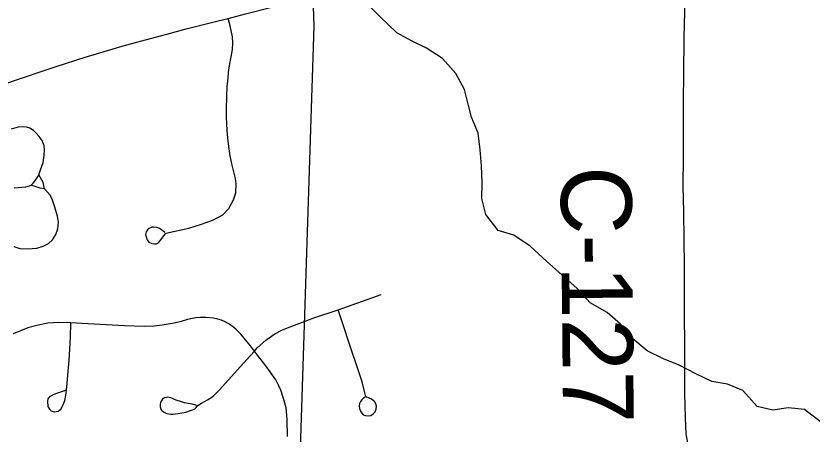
# Model space of a CAD drawing. Extents: x 0 to 34, y -5 to 22.
# Drawn here: x 2.395 to 3.035, y 19.735 to 20.071 of the extents above; entities that cross this region are included whole.
import ezdxf

# ---------------------------------------------------------------- set-up
doc = ezdxf.new("R2010")
doc.units = 0
for name, color, linetype in [('GM_X_City_Street', 7, 'Continuous'), ('GM_X_County_Road', 7, 'Continuous'), ('GM_X_County_Road_Text', 7, 'Continuous'), ('GM_X_Minor_River', 7, 'Continuous'), ('GM_X_Rail_Line', 7, 'Continuous'), ('GM_X_State_Route', 7, 'Continuous')]:
    doc.layers.add(name, color=color, linetype=linetype)

msp = doc.modelspace()

# ---------------------------------------------------------------- linework, layer by layer
at = {"layer": 'GM_X_City_Street'}
for points in [[(2.51469, 19.89713), (2.51174, 19.89956), (2.51027, 19.90044), (2.50828, 19.90133), (2.50571, 19.90162), (2.50416, 19.9014), (2.5021, 19.90044), (2.50062, 19.89934), (2.49974, 19.89787), (2.49923, 19.89559), (2.49952, 19.89368), (2.50033, 19.89146), (2.50181, 19.88955), (2.50409, 19.8883), (2.50622, 19.88801), (2.50784, 19.88815), (2.50968, 19.88903), (2.51123, 19.89102), (2.51321, 19.89375), (2.51534, 19.89661), (2.53404, 19.90067), (2.54398, 19.90383), (2.55376, 19.90744), (2.5612, 19.91156), (2.5662, 19.91656), (2.56981, 19.92348), (2.57165, 19.92908), (2.57209, 19.93636), (2.57136, 19.94078), (2.56878, 19.95138), (2.56724, 19.95881), (2.56605, 19.96646), (2.5654, 19.97324), (2.56473, 19.97934), (2.56414, 19.99031), (2.56422, 19.99613), (2.56436, 20.00687), (2.56466, 20.01438), (2.56547, 20.02159), (2.56591, 20.02579), (2.56657, 20.03145), (2.56804, 20.03859), (2.569, 20.04433), (2.56937, 20.04978), (2.56915, 20.05449), (2.56709, 20.06347), (2.56544, 20.06946)], [(2.39351, 19.9331), (2.40293, 19.9339), (2.40603, 19.9347), (2.40736, 19.9354), (2.40885, 19.93695), (2.41074, 19.93941), (2.41287, 19.94263), (2.41346, 19.94352), (2.41487, 19.94772), (2.41691, 19.95364), (2.41773, 19.95926), (2.41804, 19.96396), (2.41773, 19.96702), (2.41609, 19.9711), (2.41374, 19.97447), (2.4112, 19.97713), (2.40905, 19.97928), (2.40609, 19.98111), (2.40344, 19.98192), (2.40014, 19.98225), (2.39669, 19.98203), (2.39114, 19.9804)], [(2.39334, 19.88588), (2.39805, 19.88439), (2.40431, 19.8841), (2.41189, 19.88461), (2.41689, 19.88634), (2.4212, 19.88835), (2.4243, 19.8914), (2.42717, 19.8957), (2.42872, 19.90013), (2.42918, 19.90541), (2.42832, 19.91041), (2.42636, 19.91747), (2.42441, 19.92327), (2.42241, 19.9273), (2.41804, 19.93229), (2.41747, 19.93505), (2.41678, 19.93746), (2.41346, 19.94352)], [(2.41804, 19.93229), (2.41436, 19.93287), (2.40897, 19.93482), (2.40736, 19.9354)], [(2.54063, 19.75812), (2.53666, 19.75906), (2.53337, 19.75973), (2.53046, 19.76033), (2.52713, 19.76121), (2.52445, 19.76212), (2.5223, 19.76298), (2.52032, 19.76388), (2.5193, 19.76426), (2.51822, 19.76458), (2.51711, 19.76465), (2.51594, 19.76458), (2.51431, 19.76418), (2.51365, 19.76378), (2.51282, 19.76321), (2.51222, 19.76242), (2.51175, 19.76167), (2.51114, 19.76035), (2.51082, 19.75916), (2.51091, 19.75705), (2.5114, 19.7552), (2.51191, 19.75434), (2.51239, 19.7538), (2.51402, 19.75281), (2.51606, 19.75176), (2.51773, 19.75139), (2.5194, 19.7512), (2.52112, 19.7511), (2.52547, 19.75156), (2.52841, 19.75213), (2.53006, 19.75246), (2.53228, 19.7531), (2.53459, 19.75371), (2.53604, 19.75425), (2.53766, 19.75493), (2.53866, 19.75549), (2.53919, 19.75592), (2.53991, 19.75658), (2.54048, 19.7573), (2.54101, 19.75792), (2.54184, 19.75853), (2.54402, 19.76003), (2.54646, 19.76137), (2.54885, 19.76272), (2.55161, 19.76429), (2.55411, 19.76621), (2.55849, 19.7707), (2.5776, 19.79197), (2.58663, 19.80177), (2.5889, 19.80438), (2.59573, 19.81056), (2.60316, 19.81563), (2.60858, 19.81872), (2.61319, 19.82064), (2.63521, 19.82874), (2.65385, 19.8349), (2.68846, 19.84725)], [(2.67573, 19.76469), (2.67435, 19.76398), (2.67293, 19.76263), (2.67194, 19.76127), (2.67119, 19.75957), (2.67072, 19.75759), (2.67107, 19.75555), (2.67183, 19.7534), (2.67282, 19.75188), (2.6741, 19.75065), (2.67602, 19.75007), (2.67824, 19.74972), (2.68011, 19.75007), (2.68215, 19.75141), (2.68354, 19.75293), (2.68453, 19.7552), (2.68471, 19.75759), (2.68424, 19.75951), (2.68302, 19.76135), (2.68208, 19.76219), (2.68062, 19.76316), (2.67891, 19.76398), (2.67642, 19.76497), (2.67583, 19.76618), (2.67504, 19.76925), (2.67311, 19.77705), (2.66921, 19.78917), (2.66478, 19.80269), (2.65639, 19.82775), (2.65385, 19.8349)], [(2.6132, 19.73309), (2.61301, 19.74683), (2.61214, 19.75609), (2.60989, 19.76369), (2.60785, 19.77031), (2.60609, 19.7744), (2.60385, 19.77878), (2.59917, 19.78522), (2.59568, 19.78995), (2.58919, 19.7985), (2.58663, 19.80177), (2.58355, 19.80606), (2.57977, 19.81066), (2.57575, 19.81547), (2.5718, 19.81942), (2.56884, 19.8218), (2.56563, 19.82402), (2.56305, 19.82546), (2.56025, 19.82665), (2.55717, 19.82764), (2.55368, 19.82826), (2.54763, 19.82875), (2.54323, 19.82891), (2.53962, 19.82858), (2.53683, 19.82805), (2.53296, 19.82719), (2.5277, 19.82559), (2.52215, 19.82431), (2.51249, 19.82262), (2.50588, 19.82201), (2.49802, 19.82168), (2.4822, 19.82217), (2.44817, 19.82413), (2.43916, 19.82451), (2.42918, 19.82485), (2.42063, 19.82427), (2.41278, 19.82275), (2.40448, 19.82045), (2.39264, 19.81564)], [(2.43489, 19.77013), (2.42673, 19.76751), (2.42436, 19.76636), (2.42187, 19.76502), (2.42072, 19.76343), (2.42028, 19.76139), (2.4206, 19.75717), (2.42193, 19.755), (2.42341, 19.75366), (2.42564, 19.7529), (2.42902, 19.75341), (2.431, 19.755), (2.43253, 19.75762), (2.43419, 19.76215), (2.43502, 19.76643), (2.43553, 19.77028), (2.43629, 19.77606), (2.437, 19.78538), (2.4377, 19.79432), (2.43872, 19.81264), (2.43916, 19.82451)]]:
    msp.add_lwpolyline(points, dxfattribs=at)
at = {"layer": 'GM_X_County_Road'}
for points in [[(2.93185, 20.05259), (2.93213, 20.0657), (2.93245, 20.07343), (2.93231, 20.10676), (2.9322, 20.12011), (2.93187, 20.1263), (2.931, 20.13313), (2.92938, 20.14051), (2.92634, 20.1493), (2.92198, 20.16002)], [(2.93138, 19.99378), (2.93136, 20.00179), (2.93159, 20.02579), (2.93185, 20.05259)], [(2.93124, 19.93437), (2.93148, 19.95777), (2.93138, 19.99378)], [(2.933, 19.74826), (2.93258, 19.76765), (2.93228, 19.86992), (2.93173, 19.91388), (2.93124, 19.93437)], [(2.94681, 19.69323), (2.94, 19.70948), (2.93687, 19.71869), (2.93546, 19.7244), (2.93454, 19.72937), (2.93368, 19.73532), (2.933, 19.74826)]]:
    msp.add_lwpolyline(points, dxfattribs=at)
at = {"layer": 'GM_X_Minor_River'}
msp.add_lwpolyline([(3.04162, 19.74499), (3.02859, 19.75474), (3.01565, 19.75611), (3.00312, 19.75445), (2.99055, 19.75735), (2.979, 19.77016), (2.96678, 19.77535), (2.95421, 19.77749), (2.94122, 19.78343), (2.92784, 19.79051), (2.91524, 19.79569), (2.90224, 19.80201), (2.89073, 19.81177), (2.88071, 19.82346), (2.86997, 19.83285), (2.85657, 19.84068), (2.8458, 19.85236), (2.8339, 19.86288), (2.82123, 19.87415), (2.80817, 19.88618), (2.79515, 19.89516), (2.78256, 19.89882), (2.77253, 19.91165), (2.76935, 19.92455), (2.76958, 19.93749), (2.76906, 19.9508), (2.76815, 19.96372), (2.76648, 19.97702), (2.76102, 19.9899), (2.75863, 19.99939), (2.75544, 20.01228), (2.74846, 20.02514), (2.73768, 20.0372), (2.72505, 20.04542), (2.71282, 20.05137), (2.70096, 20.05771), (2.68751, 20.07087), (2.67674, 20.08178)], dxfattribs=at)
at = {"layer": 'GM_X_Rail_Line'}
msp.add_lwpolyline([(2.61904, 19.58233), (2.63463, 20.0632), (2.62325, 20.40582), (2.54391, 20.54005), (2.49787, 20.60374), (2.44792, 20.64979)], dxfattribs=at)
at = {"layer": 'GM_X_State_Route'}
msp.add_line((2.51615, 20.05686), (2.52884, 20.06032), dxfattribs=at)
for points in [[(2.52884, 20.06032), (2.53172, 20.0611), (2.55745, 20.06744), (2.56544, 20.06946), (2.57938, 20.07303), (2.60069, 20.07835), (2.62266, 20.08386), (2.63235, 20.08618), (2.63703, 20.0873), (2.65183, 20.09126), (2.68435, 20.09949)], [(2.4274, 20.03066), (2.45063, 20.03815), (2.48295, 20.04781), (2.51615, 20.05686)], [(2.28084, 19.97472), (2.2983, 19.98228), (2.30804, 19.98642), (2.34677, 20.00169), (2.37653, 20.01332), (2.39308, 20.01913), (2.42343, 20.02938), (2.4274, 20.03066)]]:
    msp.add_lwpolyline(points, dxfattribs=at)

# ---------------------------------------------------------------- texts
at = {"layer": 'GM_X_County_Road_Text'}
msp.add_text('C-127', height=0.056818, rotation=270.54688, dxfattribs=at).set_placement((2.83273, 19.95035))

doc.saveas('drawing.dxf')
